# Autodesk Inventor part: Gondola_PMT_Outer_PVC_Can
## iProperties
Shininess: 64.0
Length Units: 11272
Angle Units: 11279
Time Units: 11290
Mass Units: 11286
Length Display Precision: 3
Angle Display Precision: 2
Compacted: True
Part Number: Gondola_PMT_Outer_PVC_Can
Document SubType Name: Modeling
Created: 2004-08
Designer: John Blackburn
Manufacturer: Standard
Standards Organization: Custom
Material: PVC-Piping
Density: 0.0
Volumn: 0.0
Area: 0.0
PropertySet Name: Model Information
Control State: 0
Master: False
Checked Out: False
Author: John Blackburn
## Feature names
1. Base1
